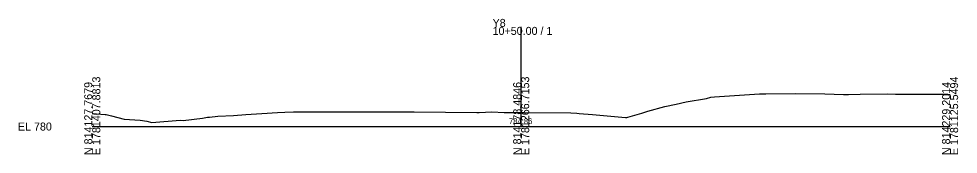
# Model space of a CAD drawing. Extents: x -26 to 303, y -10 to 5036.
# Drawn here: x -25.7 to 302.8, y 490.3 to 537.7 of the extents above; entities that cross this region are included whole.
import ezdxf

# ---------------------------------------------------------------- set-up
doc = ezdxf.new("R2010")
doc.units = 0
for name, color, linetype in [('Exist Cross Section Cell', 7, 'Continuous'), ('Exist XS Center Line Elevation Label', 7, 'Continuous'), ('Exist XS Ground Line', 7, 'Continuous')]:
    doc.layers.add(name, color=color, linetype=linetype)

msp = doc.modelspace()

# ---------------------------------------------------------------- linework, layer by layer
at = {"layer": 'Exist Cross Section Cell'}
for p, q in [((150, 500), (150, 534.88)), ((0, 500), (150, 500)), ((150, 500), (300, 500))]:
    msp.add_line(p, q, dxfattribs=at)
at = {"layer": 'Exist XS Ground Line'}
for p, q in [((207.75, 508.7), (214.81, 509.83)), ((214.81, 509.83), (216.27, 510.25)), ((216.27, 510.25), (217.59, 510.41)), ((217.59, 510.41), (233.39, 511.46)), ((233.39, 511.46), (235.59, 511.49)), ((235.59, 511.49), (245.78, 511.62)), ((245.78, 511.62), (256.22, 511.4)), ((256.22, 511.4), (262.69, 511.27)), ((262.69, 511.27), (264.51, 511.27)), ((264.51, 511.27), (268.51, 511.32)), ((268.51, 511.32), (277.99, 511.46)), ((277.99, 511.46), (280.87, 511.38)), ((280.87, 511.38), (286.26, 511.32)), ((286.26, 511.32), (299.23, 511.3)), ((299.23, 511.3), (300, 511.27)), ((194.25, 505.35), (200.29, 507)), ((200.29, 507), (204.26, 507.84)), ((204.26, 507.84), (207.75, 508.7)), ((0, 504.54), (4.57, 504.23)), ((4.57, 504.23), (4.9, 504.17)), ((4.9, 504.17), (6.71, 503.7)), ((6.71, 503.7), (11.12, 502.6)), ((31.79, 502.17), (38.54, 502.93)), ((38.54, 502.93), (40.25, 503.25)), ((40.25, 503.25), (40.99, 503.32)), ((40.99, 503.32), (43.86, 503.6)), ((43.86, 503.6), (49.36, 503.9)), ((49.36, 503.9), (53.76, 504.26)), ((53.76, 504.26), (59.28, 504.54)), ((59.28, 504.54), (64.8, 504.88)), ((64.8, 504.88), (67.33, 504.99)), ((67.33, 504.99), (70.38, 505.12)), ((70.38, 505.12), (75.06, 505.14)), ((75.06, 505.14), (83.16, 505.14)), ((83.16, 505.14), (85.57, 505.14)), ((85.57, 505.14), (88.97, 505.15)), ((88.97, 505.15), (98.58, 505.12)), ((98.58, 505.12), (108.58, 505.12)), ((108.58, 505.12), (111.83, 505.1)), ((111.83, 505.1), (112.2, 505.1)), ((112.2, 505.1), (112.63, 505.1)), ((112.63, 505.1), (134.46, 504.92)), ((134.46, 504.92), (135.32, 504.92)), ((135.32, 504.92), (139.77, 505.09)), ((139.77, 505.09), (144.06, 504.88)), ((144.06, 504.88), (146.93, 504.87)), ((146.93, 504.87), (148.22, 504.87)), ((148.22, 504.87), (150, 504.86)), ((150, 504.86), (151.15, 504.86)), ((151.15, 504.86), (167.36, 504.81)), ((167.36, 504.81), (169.47, 504.69)), ((169.47, 504.69), (170.27, 504.62)), ((170.27, 504.62), (174.93, 504.2)), ((174.93, 504.2), (186.52, 503.22)), ((186.52, 503.22), (186.95, 503.2)), ((186.95, 503.2), (187.3, 503.28)), ((187.3, 503.28), (192.19, 504.72)), ((192.19, 504.72), (193.55, 505.19)), ((193.55, 505.19), (194.25, 505.35)), ((11.12, 502.6), (16.77, 502.24)), ((16.77, 502.24), (19.1, 501.84)), ((19.1, 501.84), (20.86, 501.45)), ((20.86, 501.45), (30.77, 502.2)), ((30.77, 502.2), (31.79, 502.17))]:
    msp.add_line(p, q, dxfattribs=at)

# ---------------------------------------------------------------- texts
at = {"layer": 'Exist Cross Section Cell'}
for s, p in [('Y8', (140, 534.88)), ('10+50.00 / 1', (140, 532.08)), ('EL 780', (-26, 498.6))]:
    msp.add_text(s, height=2.8, dxfattribs=at).set_placement(p)
for s, p in [('E 1781407.8813', (2.8, 490)), ('E 1781266.7153', (152.8, 490)), ('E 1781125.5494', (302.8, 490)), ('N 814127.7679', (0, 490)), ('N 814178.4846', (150, 490)), ('N 814229.2014', (300, 490))]:
    msp.add_text(s, height=2.8, rotation=90, dxfattribs=at).set_placement(p)
at = {"layer": 'Exist XS Center Line Elevation Label'}
msp.add_text('784.86', height=2, dxfattribs=at).set_placement((145.73, 500.86))

doc.saveas('drawing.dxf')
